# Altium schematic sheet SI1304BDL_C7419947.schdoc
size 127 x 101 mm
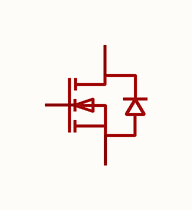
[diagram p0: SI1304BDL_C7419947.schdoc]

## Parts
Q?  si1304bdl  [SOT-323-3_L2.0-W1.3-P1.30-LS2.1-BL]  (value not drawn)

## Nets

Not connected (* = marked no-connect by the designer): Q? 1(G) 2(S) 3(D)

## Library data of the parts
Q? = si1304bdl: 漏源电压(Vdss):30V;连续漏极电流(Id):800mA;导通电阻(RDS(on)):450mΩ@4.5V,0.5A;耗散功率(Pd):360mW;阈值电压(Vgs(th)):1.2V;; Manufacturer: TECH PUBLIC(台舟); Symbol: SI1304BDL_C7419947; AddInBom: yes; ModelId: 3f7e35794ec94e50bd15d2f6547ea0a2; ModelTransform: 84.6455,94.488,0,0,0,0,0,0,0; Drain to Source Voltage: 30V; Current - Continuous Drain(Id): 800mA; Pd - Power Dissipation: 360mW; Gate Threshold Voltage (Vgs(th)): 1.2V; Gate Charge(Qg): 5.2nC@4.5V; Input Capacitance(Ciss): 146pF@15V; Reverse Transfer Capacitance (Crss@Vds): 14.8pF@15V; Output Capacitance(Coss): 18.3pF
